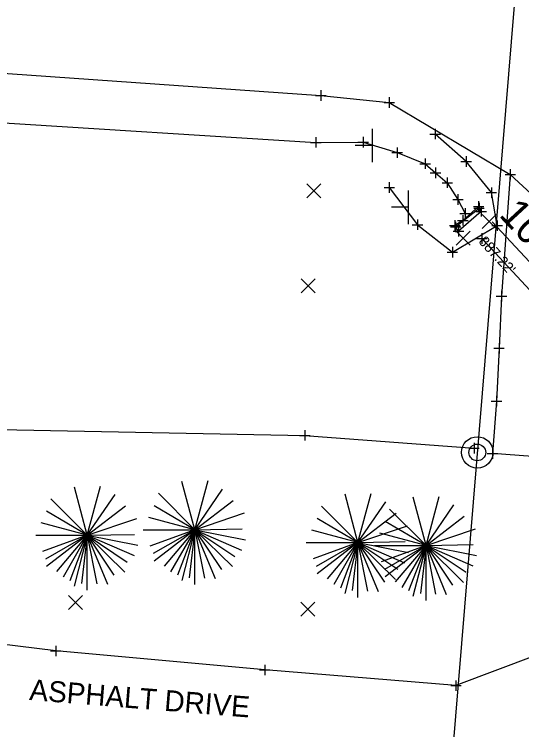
# Model space of a CAD drawing. Extents: x 1380550 to 1381945, y 468927 to 470496.
# Drawn here: x 1381506.5 to 1381555, y 469733.6 to 469802 of the extents above; entities that cross this region are included whole.
import ezdxf

# ---------------------------------------------------------------- set-up
doc = ezdxf.new("R2010")
doc.units = 0
for name, color, linetype in [('DR_X_Ditch', 7, 'Continuous'), ('DR_X_Elev_Flow', 7, 'Continuous'), ('DR_X_Storm_Sewer', 7, 'Continuous'), ('DR_X_Text', 7, 'Continuous'), ('PV_X_Driveway', 7, 'Continuous'), ('PV_X_EOP', 7, 'Continuous'), ('PV_X_Walk', 7, 'Continuous'), ('RD_X_Fence', 7, 'Continuous'), ('RD_X_Text', 7, 'Continuous'), ('RD_X_Wall', 7, 'Continuous'), ('RW_X_Esmt_General', 7, 'Continuous'), ('SC_Scratch1', 7, 'Continuous'), ('SN_X_Public', 7, 'Continuous'), ('SV_X_Break_Lines', 7, 'Continuous'), ('SV_X_Mon_Cells_Found', 7, 'Continuous'), ('SV_X_Random_Point', 7, 'Continuous'), ('SV_X_Shot_Marker', 7, 'Continuous'), ('SV_X_Top_of_Bank', 7, 'Continuous'), ('VG_X_Cells', 7, 'Continuous')]:
    doc.layers.add(name, color=color, linetype=linetype)

msp = doc.modelspace()

# ---------------------------------------------------------------- linework, layer by layer
at = {"layer": 'DR_X_Ditch'}
msp.add_lwpolyline([(1381503.968, 469791.697), (1381535.327, 469789.744), (1381539.854, 469789.762), (1381543.1, 469788.769), (1381545.782, 469787.706), (1381546.762, 469786.845), (1381547.889, 469785.893), (1381548.915, 469784.288), (1381549.587, 469782.952)], dxfattribs=at)
at = {"layer": 'DR_X_Elev_Flow'}
for p, q in [((1381551.192, 469781.065), (1381551.192, 469780.065)), ((1381550.692, 469780.565), (1381551.692, 469780.565)), ((1381551.192, 469780.565), (1381551.192, 469780.565))]:
    msp.add_line(p, q, dxfattribs=at)
at = {"layer": 'DR_X_Storm_Sewer'}
msp.add_line((1381551.192, 469780.565), (1381560.773, 469770.23), dxfattribs=at)
at = {"layer": 'DR_X_Text'}
msp.add_line((1381565.163, 469768.167), (1381552.187, 469782.164), dxfattribs=at)
at = {"layer": 'PV_X_Driveway'}
msp.add_lwpolyline([(1381566.122, 469746.805), (1381564.669, 469744.932), (1381556.427, 469740.777), (1381548.721, 469737.856), (1381530.445, 469739.354), (1381510.464, 469741.163), (1381499.816, 469742.492)], dxfattribs=at)
at = {"layer": 'PV_X_EOP'}
msp.add_lwpolyline([(1381504.028, 469796.448), (1381535.807, 469794.23), (1381542.352, 469793.559), (1381553.913, 469786.695), (1381557.537, 469783.333), (1381558.315, 469783.028), (1381558.933, 469783.936), (1381560.152, 469782.697), (1381561.946, 469780.572), (1381562.877, 469779.327), (1381563.718, 469777.647), (1381566.457, 469770.887), (1381567.072, 469765.604), (1381567.323, 469762.484), (1381566.8, 469762.436), (1381567.306, 469748.735), (1381566.899, 469746.966), (1381566.292, 469730.736), (1381565.481, 469712.75), (1381565.267, 469710.062), (1381564.074, 469691.212), (1381563.724, 469691.131), (1381563.046, 469684.218)], dxfattribs=at)
at = {"layer": 'PV_X_Walk'}
for points in [[(1381553.913, 469786.695), (1381553.074, 469775.061), (1381552.844, 469770.077), (1381552.591, 469765.034), (1381552.219, 469760.017)], [(1381557.537, 469783.333), (1381557.146, 469774.789), (1381556.682, 469769.93), (1381556.498, 469764.719), (1381556.044, 469759.732), (1381552.219, 469760.017)]]:
    msp.add_lwpolyline(points, dxfattribs=at)
at = {"layer": 'RD_X_Fence'}
msp.add_lwpolyline([(1381503.482, 469762.359), (1381534.282, 469761.756), (1381550.451, 469760.544)], dxfattribs=at)
at = {"layer": 'RD_X_Wall'}
msp.add_lwpolyline([(1381548.971, 469781.266), (1381548.69, 469781.671), (1381550.932, 469783.464), (1381551.128, 469783.153)], close=True, dxfattribs=at)
at = {"layer": 'RW_X_Esmt_General'}
msp.add_lwpolyline([(1381490.401, 469029.464), (1381590.199, 470237.184), (1380558.689, 470277.035)], dxfattribs=at)
at = {"layer": 'SN_X_Public'}
for p, q in [((1381540.699, 469791.055), (1381540.699, 469787.855)), ((1381540.699, 469789.455), (1381539.099, 469789.455)), ((1381544.163, 469785.146), (1381544.163, 469781.946)), ((1381544.163, 469783.546), (1381542.563, 469783.546))]:
    msp.add_line(p, q, dxfattribs=at)
at = {"layer": 'SV_X_Break_Lines'}
msp.add_lwpolyline([(1381550.885, 469783.638), (1381549.379, 469782.292), (1381548.61, 469781.818)], dxfattribs=at)
at = {"layer": 'SV_X_Mon_Cells_Found'}
for radius in [1.5, 0.8]:
    msp.add_circle((1381550.762, 469760.133), radius, dxfattribs=at)
at = {"layer": 'SV_X_Random_Point'}
for p, q in [((1381534.484, 469784.445), (1381535.818, 469785.78)), ((1381534.484, 469785.78), (1381535.818, 469784.445)), ((1381551.236, 469781.514), (1381552.57, 469782.849)), ((1381551.236, 469782.849), (1381552.57, 469781.514)), ((1381548.736, 469779.936), (1381550.07, 469781.271)), ((1381548.736, 469781.271), (1381550.07, 469779.936)), ((1381533.924, 469775.386), (1381535.258, 469776.721)), ((1381533.924, 469776.721), (1381535.258, 469775.386)), ((1381511.69, 469745.131), (1381513.024, 469746.466)), ((1381511.69, 469746.466), (1381513.024, 469745.131)), ((1381533.908, 469744.501), (1381535.242, 469745.836)), ((1381533.908, 469745.836), (1381535.242, 469744.501))]:
    msp.add_line(p, q, dxfattribs=at)
at = {"layer": 'SV_X_Shot_Marker'}
for p, q in [((1381535.807, 469794.73), (1381535.807, 469793.73)), ((1381535.307, 469794.23), (1381536.307, 469794.23)), ((1381535.807, 469794.23), (1381535.807, 469794.23)), ((1381542.352, 469794.059), (1381542.352, 469793.059)), ((1381541.852, 469793.559), (1381542.852, 469793.559)), ((1381542.352, 469793.559), (1381542.352, 469793.559)), ((1381546.736, 469791.045), (1381546.736, 469790.045)), ((1381535.327, 469790.244), (1381535.327, 469789.244)), ((1381539.854, 469790.262), (1381539.854, 469789.262)), ((1381546.236, 469790.545), (1381547.236, 469790.545)), ((1381546.736, 469790.545), (1381546.736, 469790.545)), ((1381534.827, 469789.744), (1381535.827, 469789.744)), ((1381535.327, 469789.744), (1381535.327, 469789.744)), ((1381539.354, 469789.762), (1381540.354, 469789.762)), ((1381539.854, 469789.762), (1381539.854, 469789.762)), ((1381543.1, 469789.269), (1381543.1, 469788.269)), ((1381542.6, 469788.769), (1381543.6, 469788.769)), ((1381543.1, 469788.769), (1381543.1, 469788.769)), ((1381545.782, 469788.206), (1381545.782, 469787.206)), ((1381549.197, 469787.919), (1381550.197, 469787.919)), ((1381549.697, 469788.419), (1381549.697, 469787.419)), ((1381549.697, 469787.919), (1381549.697, 469787.919)), ((1381545.282, 469787.706), (1381546.282, 469787.706)), ((1381545.782, 469787.706), (1381545.782, 469787.706)), ((1381546.762, 469787.345), (1381546.762, 469786.345)), ((1381546.262, 469786.845), (1381547.262, 469786.845)), ((1381546.762, 469786.845), (1381546.762, 469786.845)), ((1381553.413, 469786.695), (1381554.413, 469786.695)), ((1381553.413, 469786.695), (1381554.413, 469786.695)), ((1381553.913, 469787.195), (1381553.913, 469786.195)), ((1381553.913, 469787.195), (1381553.913, 469786.195)), ((1381553.913, 469786.695), (1381553.913, 469786.695)), ((1381553.913, 469786.695), (1381553.913, 469786.695)), ((1381542.349, 469785.939), (1381542.349, 469784.939)), ((1381547.389, 469785.893), (1381548.389, 469785.893)), ((1381547.889, 469786.393), (1381547.889, 469785.393)), ((1381547.889, 469785.893), (1381547.889, 469785.893)), ((1381541.849, 469785.439), (1381542.849, 469785.439)), ((1381542.349, 469785.439), (1381542.349, 469785.439)), ((1381552.106, 469785.449), (1381552.106, 469784.449)), ((1381548.915, 469784.788), (1381548.915, 469783.788)), ((1381551.606, 469784.949), (1381552.606, 469784.949)), ((1381552.106, 469784.949), (1381552.106, 469784.949)), ((1381548.415, 469784.288), (1381549.415, 469784.288)), ((1381548.915, 469784.288), (1381548.915, 469784.288)), ((1381550.885, 469784.138), (1381550.885, 469783.138)), ((1381550.932, 469783.964), (1381550.932, 469782.964)), ((1381549.587, 469783.452), (1381549.587, 469782.452)), ((1381550.385, 469783.638), (1381551.385, 469783.638)), ((1381550.432, 469783.464), (1381551.432, 469783.464)), ((1381550.628, 469783.153), (1381551.628, 469783.153)), ((1381550.885, 469783.638), (1381550.885, 469783.638)), ((1381550.932, 469783.464), (1381550.932, 469783.464)), ((1381551.128, 469783.653), (1381551.128, 469782.653)), ((1381551.128, 469783.153), (1381551.128, 469783.153)), ((1381549.087, 469782.952), (1381550.087, 469782.952)), ((1381549.379, 469782.792), (1381549.379, 469781.792)), ((1381549.587, 469782.952), (1381549.587, 469782.952)), ((1381544.552, 469781.887), (1381545.552, 469781.887)), ((1381545.052, 469782.387), (1381545.052, 469781.387)), ((1381545.052, 469781.887), (1381545.052, 469781.887)), ((1381548.11, 469781.818), (1381549.11, 469781.818)), ((1381548.61, 469782.318), (1381548.61, 469781.318)), ((1381548.61, 469781.818), (1381548.61, 469781.818)), ((1381548.69, 469782.171), (1381548.69, 469781.171)), ((1381548.879, 469782.292), (1381549.879, 469782.292)), ((1381548.971, 469781.766), (1381548.971, 469780.766)), ((1381549.379, 469782.292), (1381549.379, 469782.292)), ((1381552.159, 469781.797), (1381553.159, 469781.797)), ((1381552.659, 469782.297), (1381552.659, 469781.297)), ((1381552.659, 469781.797), (1381552.659, 469781.797)), ((1381548.19, 469781.671), (1381549.19, 469781.671)), ((1381548.471, 469781.266), (1381549.471, 469781.266)), ((1381548.69, 469781.671), (1381548.69, 469781.671)), ((1381548.971, 469781.266), (1381548.971, 469781.266)), ((1381548.385, 469779.756), (1381548.385, 469778.756)), ((1381547.885, 469779.256), (1381548.885, 469779.256)), ((1381548.385, 469779.256), (1381548.385, 469779.256)), ((1381552.574, 469775.061), (1381553.574, 469775.061)), ((1381553.074, 469775.561), (1381553.074, 469774.561)), ((1381553.074, 469775.061), (1381553.074, 469775.061)), ((1381552.844, 469770.577), (1381552.844, 469769.577)), ((1381552.344, 469770.077), (1381553.344, 469770.077)), ((1381552.844, 469770.077), (1381552.844, 469770.077)), ((1381552.591, 469765.534), (1381552.591, 469764.534)), ((1381552.091, 469765.034), (1381553.091, 469765.034)), ((1381552.591, 469765.034), (1381552.591, 469765.034)), ((1381534.282, 469762.256), (1381534.282, 469761.256)), ((1381533.782, 469761.756), (1381534.782, 469761.756)), ((1381534.282, 469761.756), (1381534.282, 469761.756)), ((1381550.451, 469761.044), (1381550.451, 469760.044)), ((1381549.951, 469760.544), (1381550.951, 469760.544)), ((1381550.451, 469760.544), (1381550.451, 469760.544)), ((1381551.719, 469760.017), (1381552.719, 469760.017)), ((1381551.719, 469760.017), (1381552.719, 469760.017)), ((1381552.219, 469760.517), (1381552.219, 469759.517)), ((1381552.219, 469760.517), (1381552.219, 469759.517)), ((1381552.219, 469760.017), (1381552.219, 469760.017)), ((1381552.219, 469760.017), (1381552.219, 469760.017)), ((1381510.464, 469741.663), (1381510.464, 469740.663)), ((1381509.964, 469741.163), (1381510.964, 469741.163)), ((1381510.464, 469741.163), (1381510.464, 469741.163)), ((1381530.445, 469739.854), (1381530.445, 469738.854)), ((1381529.945, 469739.354), (1381530.945, 469739.354)), ((1381530.445, 469739.354), (1381530.445, 469739.354)), ((1381548.721, 469738.356), (1381548.721, 469737.356)), ((1381548.721, 469738.356), (1381548.721, 469737.356)), ((1381548.221, 469737.856), (1381549.221, 469737.856)), ((1381548.221, 469737.856), (1381549.221, 469737.856)), ((1381548.721, 469737.856), (1381548.721, 469737.856)), ((1381548.721, 469737.856), (1381548.721, 469737.856))]:
    msp.add_line(p, q, dxfattribs=at)
at = {"layer": 'SV_X_Top_of_Bank'}
msp.add_lwpolyline([(1381542.349, 469785.439), (1381545.052, 469781.887), (1381548.385, 469779.256), (1381552.659, 469781.797), (1381552.106, 469784.949), (1381549.697, 469787.919), (1381546.736, 469790.545)], dxfattribs=at)
at = {"layer": 'VG_X_Cells'}
for p, q in [((1381523.769, 469752.746), (1381522.534, 469757.359)), ((1381523.769, 469752.746), (1381525.026, 469757.444)), ((1381513.488, 469752.215), (1381512.253, 469756.828)), ((1381513.488, 469752.215), (1381514.745, 469756.913)), ((1381523.769, 469752.746), (1381526.424, 469756.631)), ((1381513.488, 469752.215), (1381516.143, 469756.1)), ((1381523.769, 469752.746), (1381520.279, 469756.233)), ((1381539.354, 469751.52), (1381538.119, 469756.133)), ((1381539.354, 469751.52), (1381540.611, 469756.218)), ((1381545.86, 469751.235), (1381544.625, 469755.849)), ((1381545.86, 469751.235), (1381547.117, 469755.934)), ((1381513.488, 469752.215), (1381509.998, 469755.701)), ((1381523.769, 469752.746), (1381527.426, 469755.551)), ((1381539.354, 469751.52), (1381542.009, 469755.405)), ((1381545.86, 469751.235), (1381548.515, 469755.12)), ((1381513.488, 469752.215), (1381509.581, 469754.511)), ((1381513.488, 469752.215), (1381517.145, 469755.019)), ((1381523.769, 469752.746), (1381519.862, 469755.043)), ((1381539.354, 469751.52), (1381535.864, 469755.007)), ((1381545.86, 469751.235), (1381542.37, 469754.722)), ((1381513.488, 469752.215), (1381518.225, 469753.821)), ((1381523.769, 469752.746), (1381519.356, 469753.929)), ((1381523.769, 469752.746), (1381528.506, 469754.353)), ((1381539.354, 469751.52), (1381535.447, 469753.817)), ((1381539.354, 469751.52), (1381543.011, 469754.325)), ((1381545.86, 469751.235), (1381549.517, 469754.04)), ((1381513.488, 469752.215), (1381509.075, 469753.398)), ((1381539.354, 469751.52), (1381544.091, 469753.127)), ((1381545.86, 469751.235), (1381541.953, 469753.532)), ((1381518.834, 469752.746), (1381523.769, 469752.746)), ((1381523.769, 469752.746), (1381519.479, 469751.184)), ((1381523.769, 469752.746), (1381519.786, 469750.464)), ((1381523.769, 469752.746), (1381519.862, 469749.751)), ((1381523.769, 469752.746), (1381520.824, 469749.279)), ((1381523.769, 469752.746), (1381521.451, 469748.731)), ((1381523.769, 469752.746), (1381522.104, 469748.406)), ((1381523.769, 469752.746), (1381522.506, 469747.889)), ((1381523.769, 469752.746), (1381523.227, 469748.154)), ((1381523.769, 469752.746), (1381528.279, 469752.838)), ((1381523.769, 469747.506), (1381523.769, 469752.746)), ((1381523.769, 469752.746), (1381524.691, 469748.109)), ((1381523.769, 469752.746), (1381525.702, 469748.078)), ((1381523.769, 469752.746), (1381526.306, 469748.953)), ((1381523.769, 469752.746), (1381527.357, 469749.224)), ((1381523.769, 469752.746), (1381527.591, 469750.191)), ((1381523.769, 469752.746), (1381528.234, 469750.804)), ((1381523.769, 469752.746), (1381528.597, 469751.788)), ((1381539.354, 469751.52), (1381534.941, 469752.703)), ((1381545.86, 469751.235), (1381541.447, 469752.419)), ((1381545.86, 469751.235), (1381550.597, 469752.842)), ((1381508.553, 469752.215), (1381513.488, 469752.215)), ((1381513.488, 469752.215), (1381509.198, 469750.653)), ((1381513.488, 469752.215), (1381509.505, 469749.933)), ((1381513.488, 469752.215), (1381509.581, 469749.22)), ((1381513.488, 469752.215), (1381510.543, 469748.748)), ((1381513.488, 469752.215), (1381511.17, 469748.199)), ((1381513.488, 469752.215), (1381511.823, 469747.874)), ((1381513.488, 469752.215), (1381512.225, 469747.358)), ((1381513.488, 469752.215), (1381512.946, 469747.623)), ((1381513.488, 469752.215), (1381517.998, 469752.306)), ((1381513.488, 469746.975), (1381513.488, 469752.215)), ((1381513.488, 469752.215), (1381514.41, 469747.578)), ((1381513.488, 469752.215), (1381515.421, 469747.546)), ((1381513.488, 469752.215), (1381516.025, 469748.421)), ((1381513.488, 469752.215), (1381517.076, 469748.693)), ((1381513.488, 469752.215), (1381517.31, 469749.66)), ((1381513.488, 469752.215), (1381517.953, 469750.273)), ((1381513.488, 469752.215), (1381518.316, 469751.256)), ((1381534.419, 469751.52), (1381539.354, 469751.52)), ((1381539.354, 469751.52), (1381535.064, 469749.958)), ((1381539.354, 469751.52), (1381535.371, 469749.238)), ((1381539.354, 469751.52), (1381535.447, 469748.525)), ((1381539.354, 469751.52), (1381536.409, 469748.053)), ((1381539.354, 469751.52), (1381537.036, 469747.505)), ((1381539.354, 469751.52), (1381537.689, 469747.18)), ((1381539.354, 469751.52), (1381538.091, 469746.663)), ((1381539.354, 469751.52), (1381538.812, 469746.928)), ((1381539.354, 469751.52), (1381543.864, 469751.612)), ((1381539.354, 469746.28), (1381539.354, 469751.52)), ((1381539.354, 469751.52), (1381540.276, 469746.883)), ((1381539.354, 469751.52), (1381541.287, 469746.852)), ((1381539.354, 469751.52), (1381541.891, 469747.727)), ((1381539.354, 469751.52), (1381542.942, 469747.998)), ((1381539.354, 469751.52), (1381543.176, 469748.965)), ((1381539.354, 469751.52), (1381543.819, 469749.578)), ((1381539.354, 469751.52), (1381544.182, 469750.562)), ((1381540.925, 469751.235), (1381545.86, 469751.235)), ((1381545.86, 469751.235), (1381541.57, 469749.674)), ((1381545.86, 469751.235), (1381541.877, 469748.954)), ((1381545.86, 469751.235), (1381541.953, 469748.24)), ((1381545.86, 469751.235), (1381542.915, 469747.769)), ((1381545.86, 469751.235), (1381543.542, 469747.22)), ((1381545.86, 469751.235), (1381544.195, 469746.895)), ((1381545.86, 469751.235), (1381544.597, 469746.379)), ((1381545.86, 469751.235), (1381545.318, 469746.644)), ((1381545.86, 469751.235), (1381550.37, 469751.327)), ((1381545.86, 469745.995), (1381545.86, 469751.235)), ((1381545.86, 469751.235), (1381546.782, 469746.599)), ((1381545.86, 469751.235), (1381547.793, 469746.567)), ((1381545.86, 469751.235), (1381548.397, 469747.442)), ((1381545.86, 469751.235), (1381549.448, 469747.714)), ((1381545.86, 469751.235), (1381549.682, 469748.68)), ((1381545.86, 469751.235), (1381550.325, 469749.294)), ((1381545.86, 469751.235), (1381550.688, 469750.277))]:
    msp.add_line(p, q, dxfattribs=at)

# ---------------------------------------------------------------- texts
at = {"layer": 'DR_X_Text'}
msp.add_text('10" RCP', height=2.8, rotation=312.83291, dxfattribs=at).set_placement((1381552.75, 469782.768))
at = {"layer": 'RD_X_Text'}
msp.add_text('ASPHALT DRIVE', height=2, rotation=355.44278, dxfattribs=at).set_placement((1381507.903, 469736.485))
at = {"layer": 'SC_Scratch1'}
msp.add_text("887.22'", height=1, rotation=312.83291, dxfattribs=at).set_placement((1381550.825, 469780.225))

doc.saveas('drawing.dxf')
